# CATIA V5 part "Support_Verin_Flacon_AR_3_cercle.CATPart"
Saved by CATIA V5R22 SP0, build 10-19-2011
Part number: support verin avec cercle
Bounding box of the stored display mesh (mm): x 0 to 9, y -28.5 to 28.5, z -20 to 18.5
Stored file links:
  D:\PER\CAO_PER_MODIF_2025\CAO_PER_pick&place_2024P\Sous_Ensemble_Flacon\Support_Verin_Flacon_AR_3_cercle.CATPart
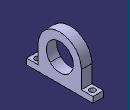
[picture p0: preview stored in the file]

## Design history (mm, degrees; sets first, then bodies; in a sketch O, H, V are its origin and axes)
Body1 (main body)
  Sketch1 on yz-plane, origin (0, 0, 0), H (0, 1, 0), V (0, 0, 1)
    arc A1 centre (0, 0) radius 11.5 from (-8.2614, -8) to (-8.2614, 8) ccw
    point P1 (-8.2614, 8)
    point P2 (-8.2614, 8)
    point P3 (-8.2614, -8)
    point P4 (-8.2614, -8)
    arc A2 centre (0, 0) radius 11.5 from (-8.2614, 8) to (-8.2614, -8) ccw
    arc A3 centre (0, 0) radius 18.5 from (18.5, 0) to (-18.5, 0) ccw
    point P5 (18.5, -20)
    line L1 (18.5, -20) -> (-18.5, -20)
    line L2 (-18.5, -15) -> (-18.5, 0)
    line L3 (18.5, 0) -> (18.5, -15)
    point P6 (-18.5, -20)
    point P7 (-18.5, 0)
    line L4 (-18.5, -20) -> (-28.5, -20)
    line L5 (-28.5, -20) -> (-28.5, -15)
    line L6 (-28.5, -15) -> (-18.5, -15)
    point P9 (-28.5, -20)
    point P10 (-28.5, -15)
    point P11 (-18.5, -15)
    point P12 (18.5, -20)
    point P13 (28.5, -20)
    point P14 (28.5, -15)
    point P15 (18.5, -15)
    line L7 (18.5, -20) -> (28.5, -20)
    line L8 (28.5, -20) -> (28.5, -15)
    line L9 (28.5, -15) -> (18.5, -15)
    radius A1 = 11.5
    distance A3 A1 = 7
    distance H L1 = 20
    length L5 = 5
    length L6 = 10
    coincidence: P1 A1, A1 A2, P7 H, P6 L2, P5 L3, P5 P12, P2 P1, P3 P4
    horizontal: L1 H, L4 H, L6 H
    vertical: L2 V, L3 V, L5 V
    tangency: L3 A3
    symmetry: P6 P12 V, P9 P13 V, P10 P14 V, P11 P15 V, L4 L7 V, L5 L8 V, L6 L9 V
  Pad1: profile Sketch1, direction (1, 0, 0), length 9
  Sketch2 on face of Pad1 from Sketch1.L6, origin (4.0945, -21.7064, -15), H (1, 0, 0), V (0, 1, 0)
    point P1 (0.4055, -1.7936)
    reference projected point E1 (-4.0945, -6.7936) from vertex [face of Pad1 from Sketch1.L5 | start face of Pad1 | face of Pad1 from Sketch1.L6]
    reference projected point E2 (4.9055, 3.2064) from vertex [face of Pad1 from Sketch1.L2 | end face of Pad1 | face of Pad1 from Sketch1.A3]
    reference projected point E3 (4.9055, -6.7936) from vertex [face of Pad1 from Sketch1.L5 | end face of Pad1 | face of Pad1 from Sketch1.L6]
    reference projected point E4 (-4.0945, 3.2064) from vertex [face of Pad1 from Sketch1.L2 | start face of Pad1 | face of Pad1 from Sketch1.A3]
    equidistance: E1 E2 P1, E3 E4 P1
  Hole1: placed by Sketch2, at (4.5, -23.5, -15) direction (0, 0, -1), diameter 5, through (limit type 6)
  Mirror1: of Hole1, about zx-plane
